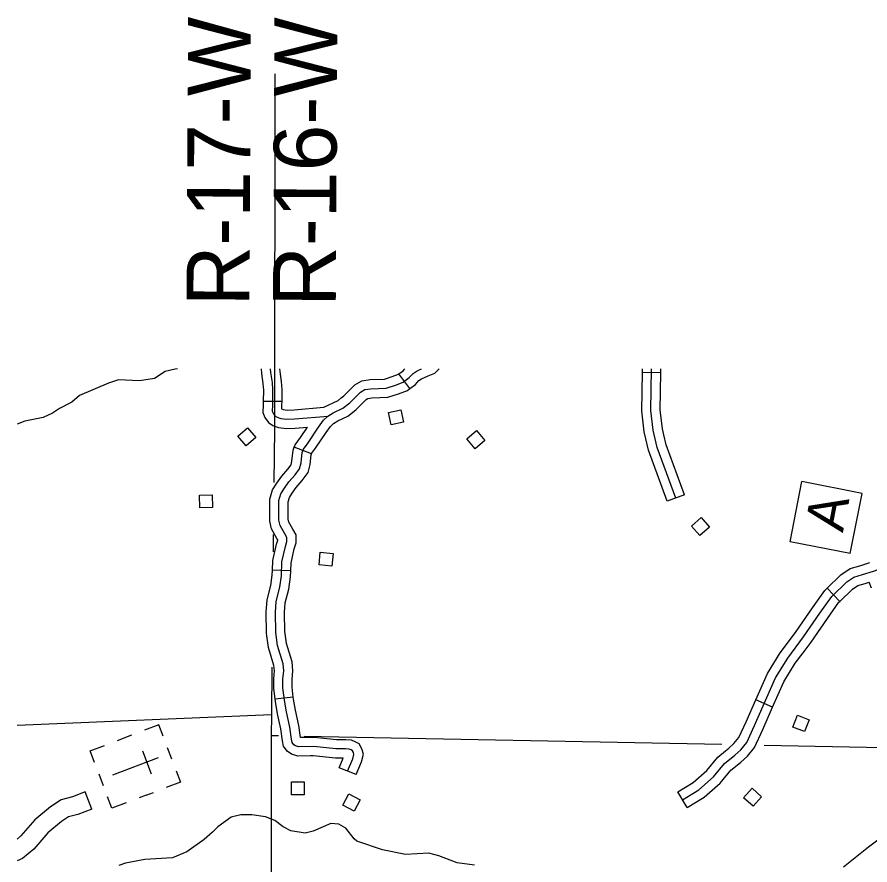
# Model space of a CAD drawing. Extents: x 1370130 to 1380143, y 377636 to 380256.
# Drawn here: x 1378043 to 1378335.4, y 378662.8 to 378953.5 of the extents above; entities that cross this region are included whole.
import ezdxf

# ---------------------------------------------------------------- set-up
doc = ezdxf.new("R2010")
doc.units = 0
for name, color, linetype in [('Level 35', 7, 'Continuous'), ('Level 4', 7, 'Continuous'), ('Level 45', 7, 'Continuous'), ('Level 46', 7, 'Continuous'), ('Level 5', 7, 'Continuous'), ('Level 56', 7, 'Continuous'), ('Level 57', 7, 'Continuous'), ('R_Draft', 7, 'Continuous')]:
    doc.layers.add(name, color=color, linetype=linetype)

msp = doc.modelspace()

# ---------------------------------------------------------------- linework, layer by layer
at = {"layer": 'Level 35'}
for points in [[(1378098.07, 378832.91), (1378097.19, 378832.81), (1378093.82, 378831.97), (1378090.17, 378829.66), (1378085.04, 378828.84), (1378077.82, 378829.17), (1378074.42, 378827.96), (1378064.47, 378823.73), (1378061.78, 378821.53), (1378057.58, 378819.32)], [(1378057.58, 378819.32), (1378055.17, 378817.68), (1378051.99, 378816.22), (1378045.7, 378814.98), (1378043.04, 378814.01)], [(1378199.79, 378662.81), (1378193.89, 378663.6), (1378187.6, 378665.99), (1378184.13, 378666.87), (1378176.22, 378666.38), (1378168.32, 378668.07), (1378159.49, 378671.03), (1378158.63, 378671.8), (1378155.69, 378675.48), (1378153.29, 378676.78), (1378150.56, 378677.06), (1378144.49, 378674.4), (1378141.74, 378673.76), (1378136.89, 378674.51), (1378134.24, 378675.93), (1378131.4, 378678.1), (1378128.21, 378679.37), (1378123.57, 378680.08), (1378119.76, 378679.99), (1378116.43, 378679.2), (1378111.81, 378675.92), (1378110.03, 378674.09), (1378107.14, 378671.59), (1378101.22, 378667.3), (1378096.34, 378665.28), (1378086.84, 378664.68), (1378080.18, 378663.43), (1378077.9, 378662.68)], [(1378345.54, 378676.91), (1378334.84, 378668.96), (1378326.28, 378662.13)]]:
    msp.add_lwpolyline(points, dxfattribs=at)
at = {"layer": 'Level 4'}
for points in [[(1378131.26, 378812.13), (1378131.06, 378793.91)], [(1378130.87, 378776.11), (1378130.81, 378770.17)], [(1378130.37, 378730.62), (1378130.2, 378714.3), (1378130.12, 378707.22), (1378130.14, 378538.28), (1378129.82, 378489.02), (1378129.99, 378485.52), (1378130.85, 378465.63)]]:
    msp.add_lwpolyline(points, dxfattribs=at)
at = {"layer": 'Level 45'}
for p, q in [((1378263.69, 378831.6), (1378257.39, 378831.72)), ((1378177.68, 378826.15), (1378173.86, 378831.16)), ((1378127.44, 378821.89), (1378133.74, 378821.81)), ((1378143.96, 378803.77), (1378138.08, 378806.04)), ((1378271.78, 378789.72), (1378265.86, 378787.56)), ((1378136.85, 378763.65), (1378130.56, 378763.91)), ((1378325.08, 378753.18), (1378320.67, 378757.68)), ((1378137.73, 378720.4), (1378131.47, 378719.63)), ((1378302.04, 378716.9), (1378296.27, 378719.43)), ((1378159.28, 378693.8), (1378153.44, 378696.17)), ((1378272.79, 378682.49), (1378269.5, 378687.87))]:
    msp.add_line(p, q, dxfattribs=at)
for points in [[(1378126.69, 378832.91), (1378126.81, 378831.34), (1378127.3, 378827.88), (1378127.49, 378825.6), (1378127.44, 378821.89)], [(1378129.85, 378832.91), (1378129.94, 378831.68), (1378130.43, 378828.24), (1378130.64, 378825.71), (1378130.57, 378820.51), (1378130.5, 378818.47), (1378130.79, 378817.76), (1378131.42, 378816.85), (1378132.19, 378816.36), (1378133.45, 378815.87), (1378135.49, 378815.66), (1378138.16, 378815.73), (1378149.72, 378816.73)], [(1378156.36, 378694.98), (1378158.08, 378699.23), (1378158.51, 378700.76), (1378158.31, 378701.42), (1378157.98, 378702.02), (1378157.52, 378702.29), (1378156.92, 378702.55), (1378155.66, 378702.62), (1378152.34, 378702.62), (1378144.71, 378703.41), (1378139.67, 378703.35), (1378138.47, 378703.68), (1378137.88, 378704.08), (1378137.35, 378704.87), (1378137.08, 378706), (1378136.55, 378710.05), (1378135.35, 378715.3), (1378134.69, 378719.28), (1378134.16, 378723.6), (1378134.16, 378726.52), (1378134.43, 378729.37), (1378134.23, 378731.83), (1378132.3, 378738.07), (1378131.71, 378742.52), (1378131.57, 378749.43), (1378131.84, 378753.21), (1378133.1, 378758.06), (1378133.63, 378761.91), (1378133.83, 378766.76), (1378135.02, 378772), (1378135.52, 378773.72), (1378135.52, 378775.13), (1378134.81, 378776.35), (1378133.19, 378779.18), (1378132.79, 378781), (1378132.79, 378783.73), (1378132.79, 378787.78), (1378133.5, 378790.1), (1378134.71, 378792.02), (1378136.22, 378794.15), (1378138.35, 378796.57), (1378139.86, 378798.7), (1378140.37, 378800.72), (1378140.77, 378804.26), (1378141.2, 378805.37), (1378142.77, 378807.55), (1378146.41, 378812.91), (1378148.07, 378815.28), (1378149.59, 378816.65), (1378151.41, 378817.81), (1378154.75, 378819.43), (1378157.12, 378821.3), (1378160.76, 378824.94), (1378162.3, 378825.8), (1378164.32, 378826.1), (1378169.58, 378826.31), (1378172.71, 378827.32), (1378175.34, 378828.33), (1378177.46, 378829.95), (1378178.78, 378831.36), (1378180.19, 378832.27), (1378181.65, 378832.91)], [(1378133.01, 378832.91), (1378133.08, 378832.02), (1378133.57, 378828.59), (1378133.8, 378825.82), (1378133.74, 378821.81)], [(1378173.86, 378831.16), (1378175.34, 378832.29), (1378175.92, 378832.91)], [(1378177.68, 378826.15), (1378179.59, 378827.61), (1378180.81, 378828.93), (1378181.69, 378829.49), (1378183.95, 378830.49), (1378186.22, 378831.42), (1378187.71, 378832.91)], [(1378258.58, 378808.89), (1378258.02, 378811.32), (1378257.15, 378818.52), (1378257.39, 378831.72)], [(1378257.39, 378831.72), (1378257.41, 378832.91)], [(1378268.82, 378788.64), (1378262.5, 378805.96), (1378261.13, 378811.87), (1378260.3, 378818.68), (1378260.56, 378832.91)], [(1378264.72, 378810.31), (1378264.23, 378812.41), (1378263.45, 378818.85), (1378263.69, 378831.6)], [(1378263.69, 378831.6), (1378263.71, 378832.91)], [(1378154.14, 378822.96), (1378155.02, 378823.66), (1378158.84, 378827.48), (1378161.27, 378828.83), (1378164.03, 378829.24), (1378169.02, 378829.44), (1378171.66, 378830.29), (1378173.79, 378831.11), (1378173.86, 378831.16)], [(1378158.04, 378818.01), (1378159.22, 378818.94), (1378162.68, 378822.4), (1378163.33, 378822.77), (1378164.62, 378822.96), (1378170.13, 378823.18), (1378173.76, 378824.35), (1378176.89, 378825.55), (1378177.68, 378826.15)], [(1378148.21, 378819.76), (1378153.06, 378822.11), (1378154.14, 378822.96)], [(1378127.44, 378821.89), (1378127.43, 378820.58), (1378127.33, 378817.91), (1378127.99, 378816.26), (1378129.19, 378814.53), (1378130.76, 378813.53), (1378132.71, 378812.78), (1378135.37, 378812.5), (1378138.34, 378812.58), (1378142.63, 378812.95)], [(1378133.74, 378821.81), (1378133.72, 378820.43), (1378133.68, 378819.16), (1378134.2, 378818.96), (1378135.61, 378818.81), (1378137.98, 378818.87), (1378148.21, 378819.76)], [(1378143.96, 378803.77), (1378143.99, 378803.86), (1378145.35, 378805.74), (1378149, 378811.12), (1378150.45, 378813.18), (1378151.51, 378814.13), (1378152.95, 378815.06), (1378156.43, 378816.74), (1378158.04, 378818.01)], [(1378138.08, 378806.04), (1378138.41, 378806.88), (1378140.19, 378809.35), (1378142.63, 378812.95)], [(1378265.86, 378787.56), (1378259.47, 378805.06), (1378258.58, 378808.89)], [(1378271.78, 378789.72), (1378265.52, 378806.86), (1378264.72, 378810.31)], [(1378129.64, 378785.09), (1378129.64, 378788.24), (1378130.6, 378791.42), (1378132.09, 378793.78), (1378133.75, 378796.1), (1378135.87, 378798.53), (1378136.95, 378800.04), (1378137.26, 378801.28), (1378137.69, 378805.02), (1378138.08, 378806.04)], [(1378135.94, 378785.09), (1378135.94, 378787.31), (1378136.39, 378788.78), (1378137.32, 378790.27), (1378138.7, 378792.19), (1378140.82, 378794.62), (1378142.77, 378797.35), (1378143.47, 378800.16), (1378143.86, 378803.5), (1378143.96, 378803.77)], [(1378130.56, 378763.91), (1378130.69, 378767.17), (1378131.97, 378772.79), (1378132.37, 378774.16), (1378132.37, 378774.28), (1378132.08, 378774.77), (1378130.22, 378778.03), (1378129.64, 378780.65), (1378129.64, 378783.73), (1378129.64, 378785.09)], [(1378136.85, 378763.65), (1378136.96, 378766.34), (1378138.07, 378771.22), (1378138.67, 378773.28), (1378138.67, 378775.99), (1378137.54, 378777.92), (1378136.16, 378780.33), (1378135.94, 378781.35), (1378135.94, 378783.73), (1378135.94, 378785.09)], [(1378320.67, 378757.68), (1378325.44, 378762.35), (1378328.57, 378764.44), (1378331.88, 378765.39), (1378335.39, 378766.52)], [(1378128.68, 378741.4), (1378128.56, 378742.28), (1378128.42, 378749.51), (1378128.72, 378753.72), (1378130, 378758.67), (1378130.49, 378762.19), (1378130.56, 378763.91)], [(1378134.92, 378742.24), (1378134.85, 378742.76), (1378134.72, 378749.35), (1378134.96, 378752.7), (1378136.19, 378757.44), (1378136.77, 378761.63), (1378136.85, 378763.65)], [(1378271.14, 378685.18), (1378276.72, 378688.59), (1378281.78, 378693.03), (1378285.5, 378697.58), (1378289.11, 378700.47), (1378291.08, 378702.33), (1378293.14, 378704.81), (1378295.83, 378710.6), (1378303.06, 378727.03), (1378307.19, 378733.75), (1378312.66, 378741.09), (1378318.24, 378749.15), (1378322.37, 378754.93), (1378327.43, 378759.89), (1378329.91, 378761.55), (1378332.8, 378762.37), (1378336.62, 378763.61), (1378338.26, 378764.09)], [(1378325.08, 378753.18), (1378329.42, 378757.44), (1378331.25, 378758.65), (1378333.72, 378759.36), (1378335.1, 378759.81)], [(1378335.95, 378757.76), (1378335.1, 378759.81)], [(1378307.42, 378739.32), (1378310.1, 378742.92), (1378315.66, 378750.96), (1378319.97, 378756.99), (1378320.67, 378757.68)], [(1378312.47, 378735.55), (1378315.22, 378739.25), (1378320.82, 378747.33), (1378324.77, 378752.88), (1378325.08, 378753.18)], [(1378131.47, 378719.63), (1378131.01, 378723.41), (1378131.01, 378726.67), (1378131.26, 378729.39), (1378131.11, 378731.23), (1378129.22, 378737.39), (1378128.68, 378741.4)], [(1378137.73, 378720.4), (1378137.31, 378723.79), (1378137.31, 378726.37), (1378137.59, 378729.36), (1378137.34, 378732.43), (1378135.39, 378738.75), (1378134.92, 378742.24)], [(1378296.27, 378719.43), (1378300.26, 378728.5), (1378304.58, 378735.52), (1378307.42, 378739.32)], [(1378302.04, 378716.9), (1378305.85, 378725.57), (1378309.8, 378731.98), (1378312.47, 378735.55)], [(1378143.57, 378700.25), (1378139.26, 378700.19), (1378137.14, 378700.78), (1378135.6, 378701.81), (1378134.41, 378703.6), (1378133.98, 378705.44), (1378133.45, 378709.5), (1378132.26, 378714.69), (1378131.57, 378718.83), (1378131.47, 378719.63)], [(1378143.49, 378706.55), (1378140.2, 378706.5), (1378140.18, 378706.57), (1378139.65, 378710.61), (1378138.45, 378715.91), (1378137.81, 378719.73), (1378137.73, 378720.4)], [(1378285.9, 378701.93), (1378287.04, 378702.85), (1378288.77, 378704.49), (1378290.46, 378706.51), (1378292.96, 378711.9), (1378296.27, 378719.43)], [(1378289.83, 378697.01), (1378291.18, 378698.1), (1378293.38, 378700.17), (1378295.83, 378703.11), (1378298.7, 378709.3), (1378302.04, 378716.9)], [(1378159.28, 378693.8), (1378161.07, 378698.21), (1378161.79, 378700.78), (1378161.23, 378702.65), (1378160.31, 378704.32), (1378158.94, 378705.1), (1378157.67, 378705.67), (1378155.74, 378705.77), (1378152.51, 378705.77), (1378144.85, 378706.57), (1378143.49, 378706.55)], [(1378153.44, 378696.17), (1378154.78, 378699.47), (1378152.18, 378699.47), (1378144.57, 378700.26), (1378143.57, 378700.25)], [(1378269.5, 378687.87), (1378274.84, 378691.13), (1378279.51, 378695.23), (1378283.27, 378699.83), (1378285.9, 378701.93)], [(1378272.79, 378682.49), (1378278.59, 378686.04), (1378284.05, 378690.84), (1378287.73, 378695.33), (1378289.83, 378697.01)]]:
    msp.add_lwpolyline(points, dxfattribs=at)
at = {"layer": 'Level 46'}
for points in [[(1378068.65, 378682.01), (1378066.37, 378687.88), (1378062.01, 378686.19), (1378058.13, 378685.22), (1378054.51, 378682.8), (1378049.13, 378678.36), (1378044.32, 378672.79), (1378043.04, 378671.7)], [(1378068.65, 378682.01), (1378063.92, 378680.17), (1378060.72, 378679.37), (1378058.28, 378677.74), (1378053.55, 378673.84), (1378048.77, 378668.3), (1378044.91, 378665.03), (1378043.04, 378664.28)]]:
    msp.add_lwpolyline(points, dxfattribs=at)
at = {"layer": 'Level 5'}
for points in [[(1378131.4, 378934.12), (1378131.26, 378812.13)], [(1378130.2, 378714.3), (1378043.04, 378710.69)], [(1378130.12, 378707.22), (1378132.6, 378707.18)], [(1378141.49, 378707), (1378284.57, 378704.23)], [(1378299.18, 378703.94), (1378340.06, 378703.15)]]:
    msp.add_lwpolyline(points, dxfattribs=at)
at = {"layer": 'Level 56'}
for points in [[(1378174.64, 378818.9), (1378175.52, 378814.62), (1378171.23, 378813.73), (1378170.34, 378818.01)], [(1378122.05, 378812.69), (1378124.89, 378809.36), (1378121.56, 378806.52), (1378118.72, 378809.84)], [(1378203.38, 378808.38), (1378200.05, 378805.55), (1378197.21, 378808.89), (1378200.54, 378811.73)], [(1378105.54, 378789.67), (1378109.91, 378789.78), (1378110.03, 378785.4), (1378105.66, 378785.28)], [(1378277.54, 378781.91), (1378280.41, 378778.62), (1378277.11, 378775.74), (1378274.24, 378779.03)], [(1378146.99, 378770.07), (1378151.34, 378769.62), (1378150.89, 378765.26), (1378146.54, 378765.71)], [(1378314.6, 378712.62), (1378313.01, 378708.54), (1378308.93, 378710.13), (1378310.51, 378714.21)], [(1378137.06, 378686.92), (1378137.06, 378691.3), (1378141.45, 378691.3), (1378141.45, 378686.92)], [(1378292.05, 378685.87), (1378294.96, 378689.13), (1378298.23, 378686.21), (1378295.32, 378682.95)], [(1378160.66, 378685.16), (1378158.61, 378681.3), (1378154.74, 378683.37), (1378156.8, 378687.22)]]:
    msp.add_lwpolyline(points, close=True, dxfattribs=at)
at = {"layer": 'Level 57'}
for p, q in [((1378308.01, 378773.66), (1378312.08, 378794.26)), ((1378332.68, 378790.2), (1378312.08, 378794.26)), ((1378328.62, 378769.59), (1378332.68, 378790.2)), ((1378328.62, 378769.59), (1378308.01, 378773.66)), ((1378082.29, 378707.31), (1378077.38, 378705.45)), ((1378096.13, 378699.07), (1378094.64, 378702.99)), ((1378086.03, 378701.99), (1378089.03, 378694.11)), ((1378091.45, 378699.56), (1378075.75, 378693.59)), ((1378083.6, 378696.58), (1378083.6, 378696.58)), ((1378083.6, 378696.58), (1378083.6, 378696.58)), ((1378071.08, 378694.04), (1378072.57, 378690.12)), ((1378087.33, 378686.76), (1378084.84, 378685.81)), ((1378087.33, 378686.76), (1378089.75, 378687.68))]:
    msp.add_line(p, q, dxfattribs=at)
for points in [[(1378093.14, 378706.94), (1378091.65, 378710.87), (1378086.74, 378709)], [(1378069.58, 378697.99), (1378068.09, 378701.92), (1378073, 378703.78)], [(1378097.61, 378695.16), (1378099.11, 378691.23), (1378094.2, 378689.37)], [(1378080.46, 378684.15), (1378075.55, 378682.29), (1378074.06, 378686.21)]]:
    msp.add_lwpolyline(points, dxfattribs=at)

# ---------------------------------------------------------------- texts
msp.add_text('A', height=13.31, rotation=78.8423, dxfattribs=at).set_placement((1378326.08, 378776.6))
at = {"layer": 'R_Draft'}
for s, p in [('R-17-W', (1378122.67, 378854.31)), ('R-16-W', (1378152.29, 378854.16))]:
    msp.add_text(s, height=21.538, rotation=89.6959, dxfattribs=at).set_placement(p)

doc.saveas('drawing.dxf')
